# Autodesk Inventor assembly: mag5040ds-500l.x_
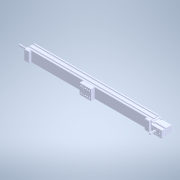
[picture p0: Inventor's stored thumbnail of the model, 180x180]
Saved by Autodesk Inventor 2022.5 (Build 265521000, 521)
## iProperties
Created: 2023-04
Part Number: mag5040ds-500l.x_
Document SubType Name: Assembly
Designer: ImaoCorp
Sending System: SOLIDWORKS 2021-2021301
MC: AMD64
MC_MODEL: Intel64 Family 6 Model 60 Stepping 3, GenuineIntel
OS: Windows_NT
FRU: Parasolid Version 32.1, build 255,  1- 1-2021
FORMAT: text
GUISE: transmit
KEY: mag5040ds-500l
FILE: mag5040ds-500l.x_t
DATE: Wed Apr 12 15:45:14 2023
Author: ImaoCorp
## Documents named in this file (4)
- X:\14_SW2022-Inv2022\00_全2023-1023新製品(TCC)まで\m\mag5040ds-500l\MAG5040DS-500L.iam
- X:\14_SW2022-Inv2022\00_全2023-1023新製品(TCC)まで\m\mag5040ds-500l\mag5040ds-500l_01.ipt
- X:\14_SW2022-Inv2022\00_全2023-1023新製品(TCC)まで\m\mag5040ds-500l\mag5040ds-500l_02.ipt
- X:\14_SW2022-Inv2022\00_全2023-1023新製品(TCC)まで\m\mag5040ds-500l\mag5040ds-500l_03.ipt
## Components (3 placed, 3 different names)
1. mag5040ds-500l_01
2. mag5040ds-500l_02
3. mag5040ds-500l_03
